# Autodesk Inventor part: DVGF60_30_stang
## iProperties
Created: 2010-04
Part Number: DVGF60_30_stang
Document SubType Name: Modeling
Designer: TB
Mass: 265.013 g
Surface Area: 347.16 cm^2
Volume: 265.013 cm^3
Density: 1 g/cm^3
Author: TB
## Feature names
1. Revolution1
2. Fillet1
3. Revolution2
4. Extrusion1
5. Extrusion2
6. Extrusion3
7. Chamfer2
8. Chamfer3
9. Chamfer4
